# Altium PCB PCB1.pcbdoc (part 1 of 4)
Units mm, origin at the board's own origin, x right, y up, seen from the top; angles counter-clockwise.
Board outline 96.27 x 122.17 mm, 4 copper layers (Top Layer, Inner1, Inner2, Bottom Layer); 129 components, 127 nets, 708 pads, 342 vias.
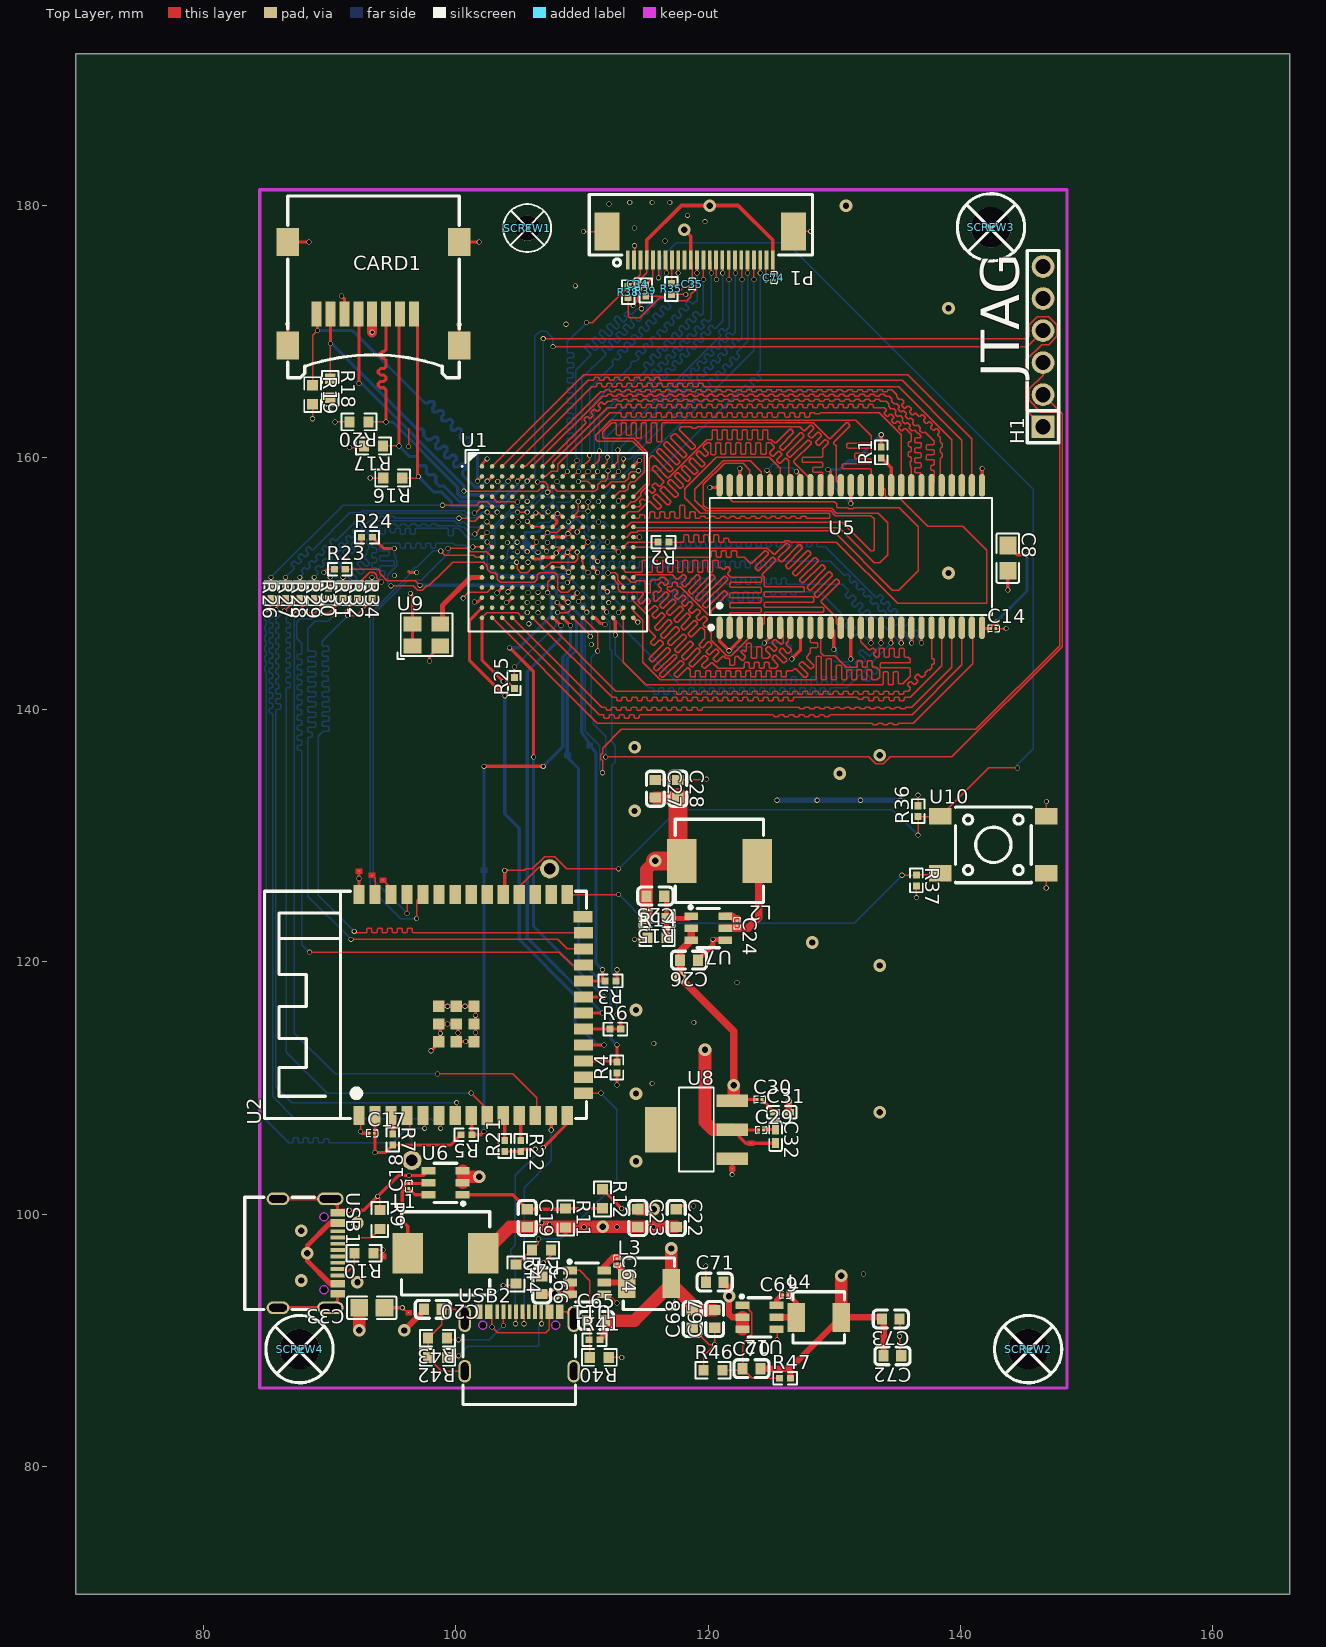
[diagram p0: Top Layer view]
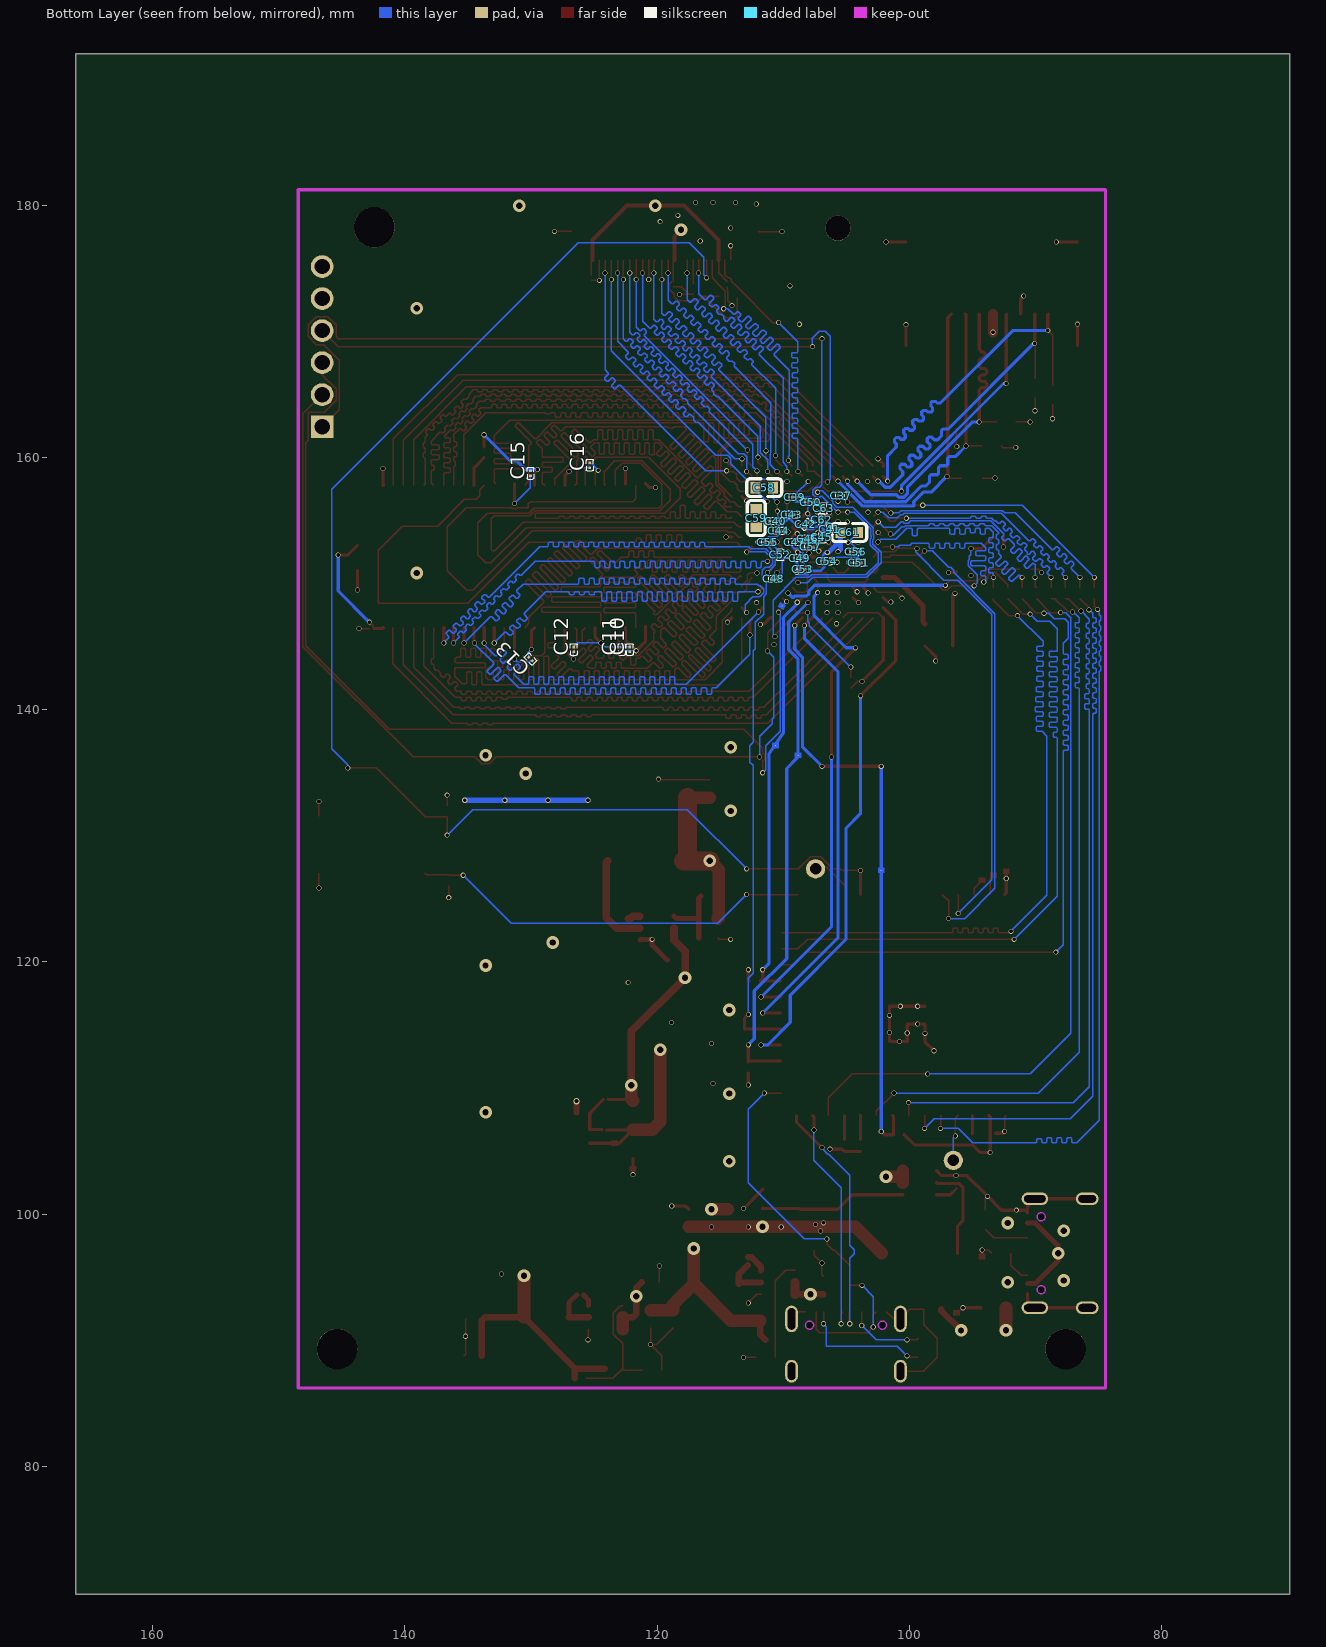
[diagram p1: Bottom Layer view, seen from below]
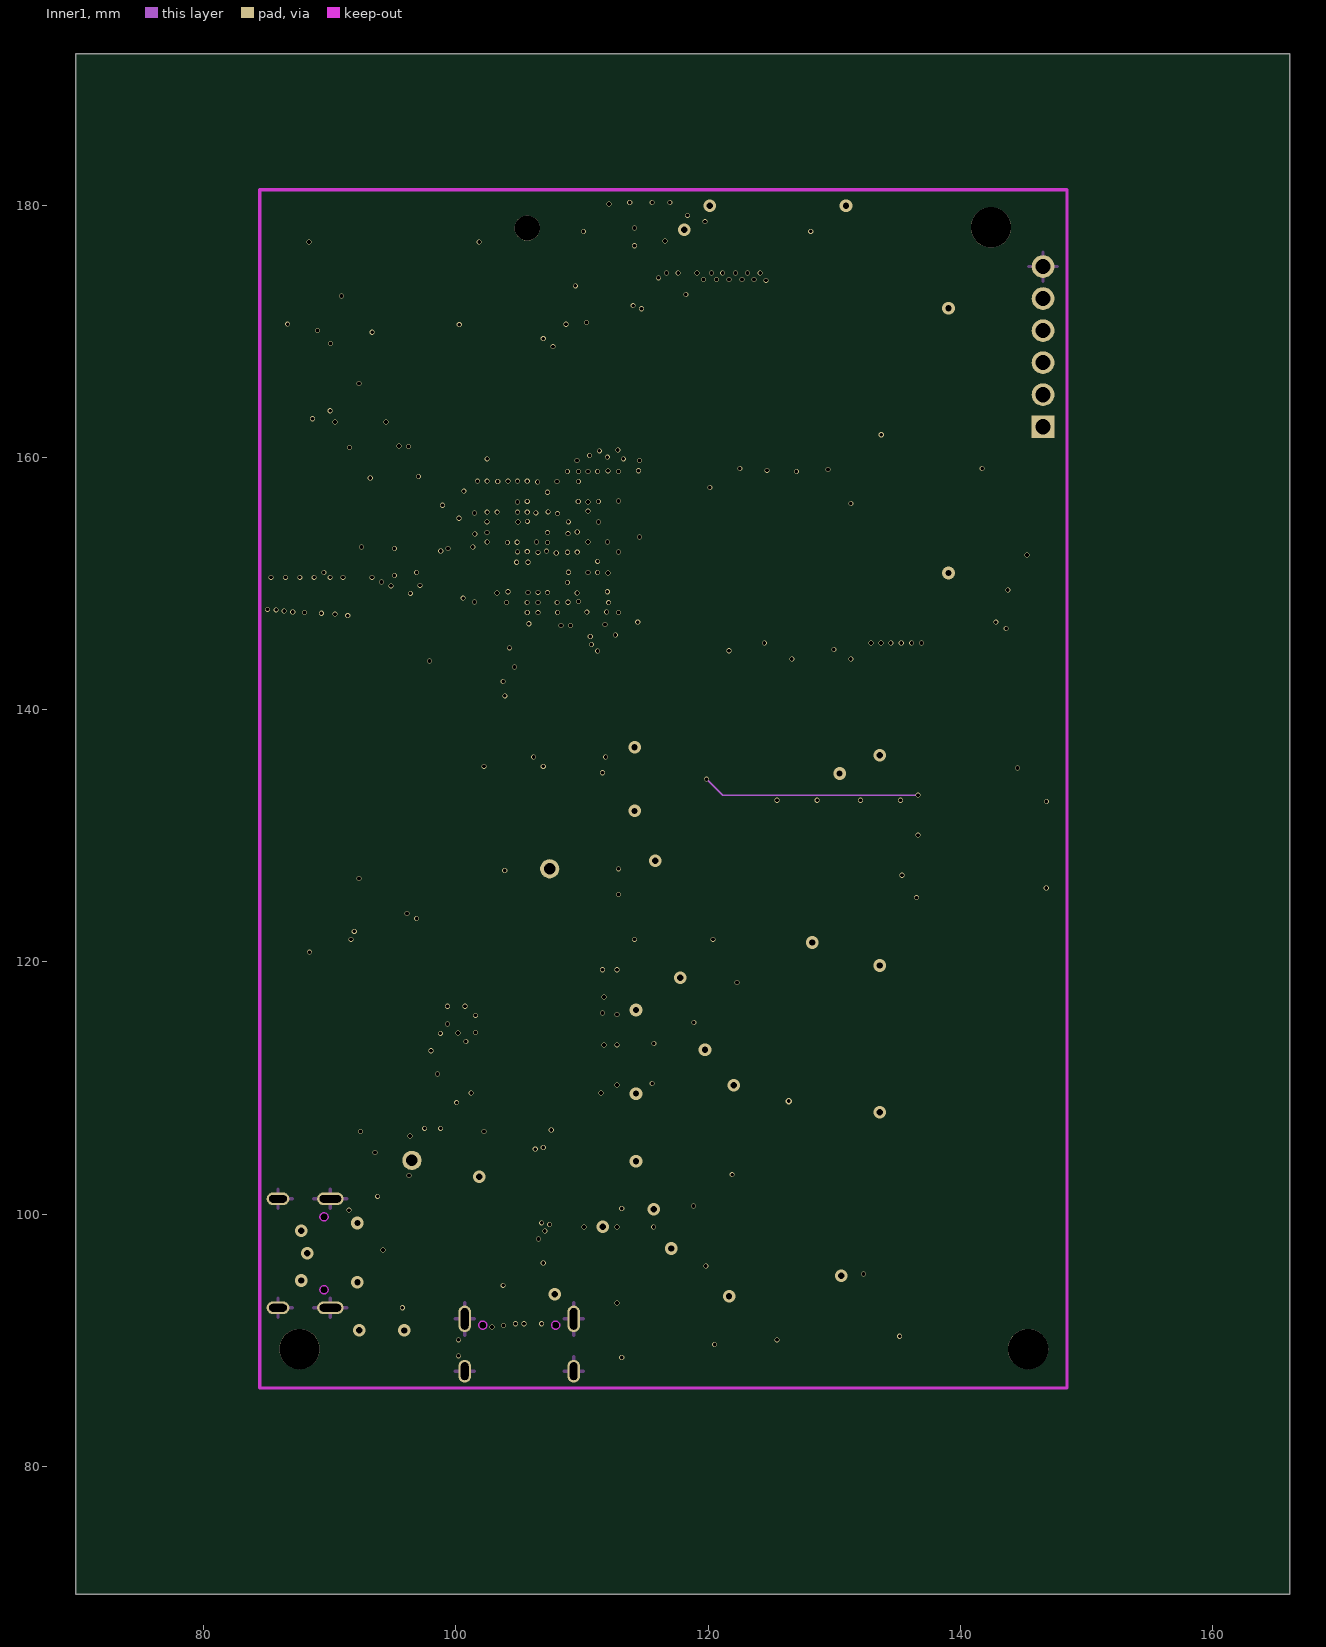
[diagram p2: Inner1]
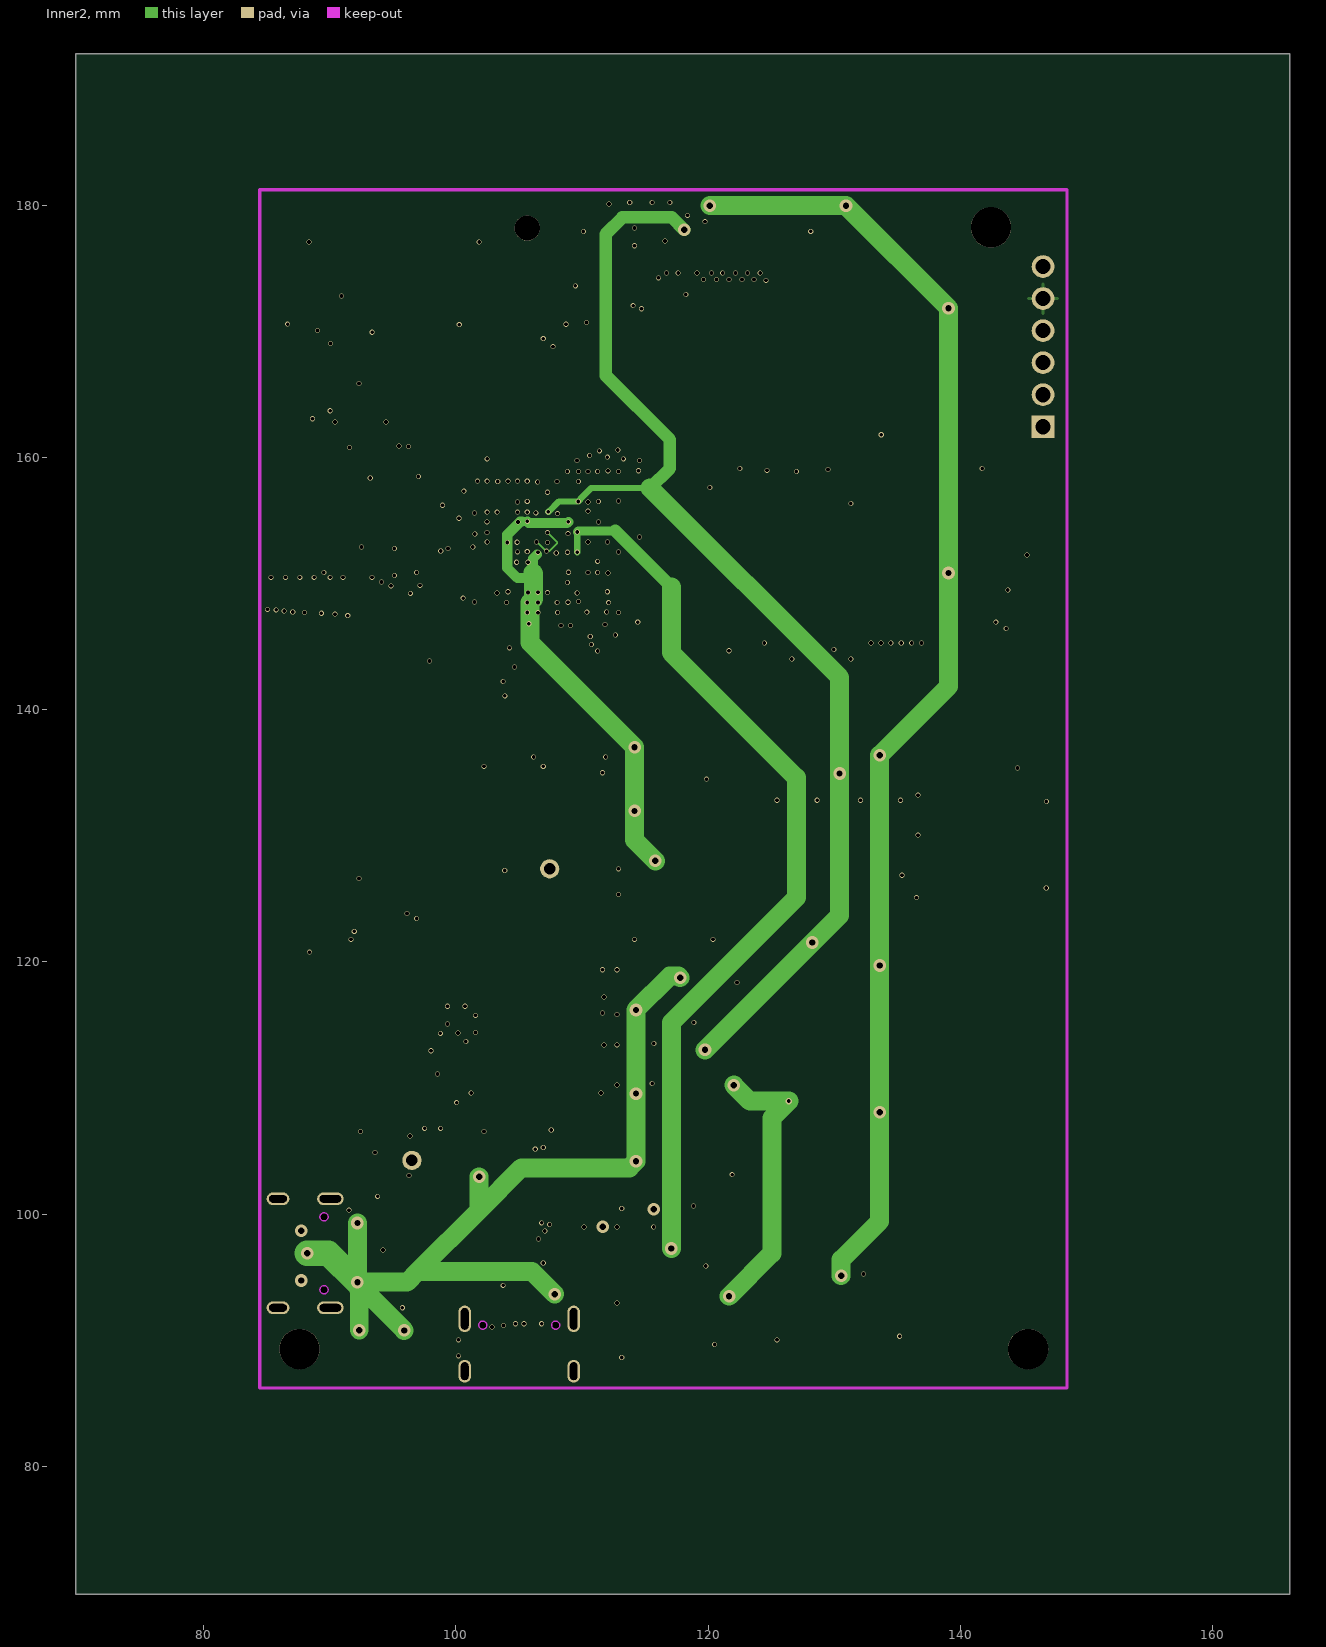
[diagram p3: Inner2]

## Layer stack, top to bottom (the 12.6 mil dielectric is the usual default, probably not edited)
Top Layer: signal copper (thickness not stored)
Dielectric: dielectric 0.32, FR-4, Dk 4.8
Inner1: signal copper (thickness not stored)
Dielectric: dielectric 0.32, FR-4, Dk 4.8
Inner2: signal copper (thickness not stored)
Dielectric: dielectric 0.32, FR-4, Dk 4.8
Bottom Layer: signal copper (thickness not stored)

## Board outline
166.116,69.85 69.85,69.85 69.85,192.024 166.116,192.024

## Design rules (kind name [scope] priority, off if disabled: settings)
BoardOutlineClearance copperThickness1oz [All] p0: genericclearance=0.254 ignorepadtopadclearanceinfootprint=FALSE except(0: Arc-SplitContinuation Track-SplitContinuation SMDPad-SplitContinuation THPad-SplitContinuation Via-SplitContinuation Fill-SplitContinuation Poly-SplitContinuation Region-SplitContinuation Text-SplitContinuation; 0.152: Track-CutoutEdge SMDPad-CutoutEdge THPad-CutoutEdge Via-CutoutEdge Region-CutoutEdge; 0.3: Track-OutlineEdge SMDPad-OutlineEdge THPad-OutlineEdge Via-OutlineEdge Fill-OutlineEdge Region-OutlineEdge Poly-OutlineEdge Text-OutlineEdge Fill-CutoutEdge)
BoardOutlineClearance copperThickness2oz [All] p0: genericclearance=0.254 ignorepadtopadclearanceinfootprint=FALSE except(0: Arc-SplitContinuation Track-SplitContinuation SMDPad-SplitContinuation THPad-SplitContinuation Via-SplitContinuation Fill-SplitContinuation Poly-SplitContinuation Region-SplitContinuation Text-SplitContinuation; 0.152: Track-CutoutEdge SMDPad-CutoutEdge THPad-CutoutEdge Via-CutoutEdge Region-CutoutEdge; 0.3: Track-OutlineEdge SMDPad-OutlineEdge THPad-OutlineEdge Via-OutlineEdge Fill-OutlineEdge Region-OutlineEdge Poly-OutlineEdge Text-OutlineEdge Fill-CutoutEdge)
Clearance copperThickness1oz [(InNet('SD_A0') OR InNet('SD_A1') OR InNet('SD_A2') OR InNet('SD_A3') OR InNet('SD_A4') OR InNet('SD_A5') OR InNet('SD_A6') OR InNet('SD_A7') OR InNet('SD_A8') OR InNet('SD_A9') OR InNet('SD_A10') OR InNet('SD_A11') OR InNet('SD_A12') OR InNet('SD_DQ15') OR InNet('SD_DQ14') OR InNet('SD_DQ8') OR InNet('SD_BA0') OR InNet('SD_BA1') OR InNet('SD_DQ9') OR InNet('SD_DQ7') OR InNet('SD_CLK') OR InNet('SD_WE_N') OR InNet('SD_DQ10') OR InNet('SD_CAS_N') OR InNet('SD_DQM1') OR InNet('SD_DQ2') OR InNet('SD_DQ3') OR InNet('SD_DQ11') OR InNet('SD_DQ12') OR InNet('SD_DQ13') OR InNet('SD_DQ0') OR InNet('SD_DQ1') OR InNet('SD_CS_N') OR InNet('SD_RAS_N') OR InNet('SD_DQ4') OR InNet('SD_DQ6') OR InNet('GND') OR InNet('SD_DQ5') OR InNet('SD_DQM0') OR InNet('$1N9437') OR InNet('+3V3') OR InNet('$1N11348') OR InNet('DOUT') OR InNet('DIN') OR InNet('CCLK') OR InNet('DONE') OR InNet('PROGRAMN') OR InNet('INITN') OR InNet('$1N11975') OR InNet('DN') OR InNet('DP') OR InNet('$1N14459') OR InNet('$1N14416') OR InNet('$1N14567') OR InNet('+5V') OR InNet('$1N16833') OR InNet('$1N16832') OR InNet('+1V1') OR InNet('$1N16834') OR InNet('+1V8') OR InNet('$1N17349') OR InNet('$1N12557') OR InNet('$1N12553') OR InNet('M_D2') OR InNet('M_D3') OR InNet('M_CMD') OR InNet('M_CLK') OR InNet('M_D0') OR InNet('M_D1') OR InNet('SDA') OR InNet('SCL') OR InNet('RESET') OR InNet('VSYNC') OR InNet('HREF') OR InNet('Y9') OR InNet('MCLK') OR InNet('Y8') OR InNet('Y7') OR InNet('PCLK') OR InNet('Y6') OR InNet('Y2') OR InNet('Y5') OR InNet('Y3') OR InNet('Y4') OR InNet('CRYSTAL') OR InNet('SSPI_CS_N') OR InNet('D0') OR InNet('D1') OR InNet('D2') OR InNet('D4') OR InNet('D3') OR InNet('D5') OR InNet('D6') OR InNet('D7') OR InNet('RX') OR InNet('TX') OR InNet('$1N29790') OR InNet('$1N29833') OR InNet('$1N29916') OR InNet('$1N29959') OR InNet('$1N30002') OR InNet('$1N30085') OR InNet('$1N30089') OR InNet('$1N30093') OR InNet('TDO') OR InNet('TDI') OR InNet('TMS') OR InNet('TCK') OR InNet('$1N33205') OR InNet('PROGRAM') OR InNet('$2N5507') OR InNet('$2N5509') OR InNet('$2N5511') OR InNet('FSDA') OR InNet('FSCL') OR InNet('+2V5') OR InNet('$1N60668') OR InNet('$1N60669') OR InNet('$1N60670') OR InNet('USB_VBUS') OR InNet('$1N63772') OR InNet('$1N63749') OR InNet('$1N63825') OR InNet('+2V8') OR InNet('$1N64402') OR InNet('$1N64401') OR InNet('$1N64403'))] p1: gap=0.178 ignorepadtopadclearanceinfootprint=FALSE except(0.099: Track-Track; 0.152: Track-SMDPad SMDPad-SMDPad Track-THPad SMDPad-THPad THPad-THPad Track-Via SMDPad-Via THPad-Via Via-Via SMDPad-Fill THPad-Fill Via-Fill Fill-Fill Track-Region SMDPad-Region THPad-Region Via-Region Region-Region Track-Poly SMDPad-Poly THPad-Poly Via-Poly Fill-Poly Region-Poly Poly-Poly Track-Text SMDPad-Text THPad-Text Via-Text Fill-Text Region-Text Poly-Text Text-Text; 0.175: Track-Hole SMDPad-Hole THPad-Hole Via-Hole Fill-Hole Region-Hole Poly-Hole Text-Hole Sheet-Hole; 0.3: Track-Fill Fill-Region Track-Sheet SMDPad-Sheet THPad-Sheet Via-Sheet Fill-Sheet Region-Sheet Poly-Sheet Text-Sheet)
Clearance copperThickness2oz [All] p1: gap=0.178 ignorepadtopadclearanceinfootprint=FALSE except(0.152: Track-SMDPad SMDPad-SMDPad Track-THPad SMDPad-THPad THPad-THPad Track-Via SMDPad-Via THPad-Via Via-Via SMDPad-Fill THPad-Fill Via-Fill Fill-Fill Track-Region SMDPad-Region THPad-Region Via-Region Region-Region Track-Poly SMDPad-Poly THPad-Poly Via-Poly Fill-Poly Region-Poly Poly-Poly Track-Text SMDPad-Text THPad-Text Via-Text Fill-Text Region-Text Poly-Text Text-Text; 0.175: Track-Hole SMDPad-Hole THPad-Hole Via-Hole Fill-Hole Region-Hole Poly-Hole Text-Hole Sheet-Hole; 0.203: Track-Track; 0.3: Track-Fill Fill-Region Track-Sheet SMDPad-Sheet THPad-Sheet Via-Sheet Fill-Sheet Region-Sheet Poly-Sheet Text-Sheet)
DiffPairsRouting differentialPair [All] p1: maxuncoupledlength=10 minlimit=6 maxlimit=6 mostfreqgap=6 toplayer_minwidth=5 toplayer_prefwidth=10 toplayer_maxwidth=100 bottomlayer_minwidth=5 bottomlayer_prefwidth=10 bottomlayer_maxwidth=100 midlayer1_minwidth=5 midlayer1_prefwidth=10 midlayer1_maxwidth=100 midlayer2_minwidth=5 midlayer2_prefwidth=10 midlayer2_maxwidth=100
PasteMaskExpansion pasteMaskExpansion [All] p1: expansion=0
PlaneConnect innerPlane [All] p1: planeconnectstyle=Relief reliefexpansion=0.508 reliefentries=4 reliefconductorwidth=0.254 reliefairgap=0.254
PolygonConnect copperRegion [All] p1: connectstyle=Relief reliefentries=4 reliefconductorwidth=10 polygonreliefangle="90 Angle" airgapwidth=10
RoutingVias viaSize [All] p1: viastyle="Through Hole" holewidth=11.811 minholewidth=11.811 maxholewidth=248.0314 width=15.748 minwidth=15.748 maxwidth=393.7008
SolderMaskExpansion solderMaskExpansion [All] p1: useseparateexpansions=TRUE expansion=2 expansionbottom=2
Width copperThickness1oz [All] p1: maxlimit=100 minlimit=4 preferedwidth=4
Width copperThickness2oz [All] p1: maxlimit=100 minlimit=8 preferedwidth=10

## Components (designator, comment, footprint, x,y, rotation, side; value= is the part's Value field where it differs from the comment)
C8 "CL21A476MQYNNNE" C0805 143.764,152.019 r270 top
C10 "GRM022R60J104KE15D" C01005 122.174,144.78 r90 bottom
C11 "GRM022R60J104KE15D" C01005 122.809,144.78 r90 bottom
C12 "GRM022R60J104KE15D" C01005 126.619,144.78 r90 bottom
C13 "GRM022R60J104KE15D" C01005 130.048,144.018 r45 bottom
C14 "GRM022R60J104KE15D" C01005 142.621,146.431 r0 top
C15 "GRM022R60J104KE15D" C01005 130.048,158.75 r90 bottom
C16 "GRM022R60J104KE15D" C01005 125.349,159.385 r90 bottom
C17 "GRM022R60J104KE15D" C01005 93.345,106.426 r0 top
C18 "GRM022R60J104KE15D" C01005 96.266,102.235 r90 top
C19 "TCC0603X7R104K500CT" C0603 105.664,99.695 r270 top
C20 "TCC0603X5R226M6R3CT" C0603 98.171,92.456 r180 top
C22 "TCC0603X5R226M6R3CT" C0603 117.475,99.695 r270 top
C23 "TCC0603X5R226M6R3CT" C0603 114.427,99.695 r270 top
C24 "GRM022R60J104KE15D" C01005 122.301,123.063 r270 top
C25 "TCC0603X7R104K500CT" C0603 115.824,125.222 r180 top
C26 "TCC0603X5R226M6R3CT" C0603 118.491,120.142 r180 top
C27 "TCC0603X5R226M6R3CT" C0603 115.824,133.731 r270 top
C28 "TCC0603X5R226M6R3CT" C0603 117.602,133.731 r270 top
C29 "GRM022R60J104KE15D" C01005 124.206,106.68 r0 top
C30 "GRM022R60J104KE15D" C01005 124.079,109.093 r0 top
C31 "GRM155R60J106ME44D" C0402 125.857,108.077 r0 top
C32 "GRM155R60J106ME44D" C0402 125.349,106.172 r270 top
C33 "CL21A476MQYNNNE" C0805 93.345,92.583 r180 top
C34 "GRM022R60J104KE15D" C01005 114.427,173.736 r270 top
C35 "GRM022R60J104KE15D" C01005 118.745,173.736 r270 top
C37 "GRM022R60J104KE15D" C01005 105.41,156.972 r180 bottom
C39 "GRM022R60J104KE15D" C01005 109.093,156.845 r180 bottom
C40 "GRM022R60J104KE15D" C01005 110.617,154.94 r180 bottom
C41 "GRM022R60J104KE15D" C01005 106.299,154.305 r90 bottom
C42 "GRM022R60J104KE15D" C01005 108.204,154.686 r135 bottom
C43 "GRM022R60J104KE15D" C01005 109.347,155.448 r180 bottom
C44 "GRM022R60J104KE15D" C01005 110.363,154.178 r180 bottom
C45 "GRM022R60J104KE15D" C01005 106.934,153.67 r270 bottom
C46 "GRM022R60J104KE15D" C01005 108.077,153.543 r180 bottom
C47 "GRM022R60J104KE15D" C01005 109.093,153.289 r0 bottom
C48 "GRM022R60J104KE15D" C01005 110.744,150.368 r180 bottom
C49 "GRM022R60J104KE15D" C01005 108.712,152.019 r180 bottom
C50 "GRM022R60J104KE15D" C01005 107.823,156.464 r180 bottom
C51 "GRM022R60J104KE15D" C01005 104.013,151.638 r180 bottom
C52 "GRM022R60J104KE15D" C01005 110.236,152.273 r270 bottom
C53 "GRM022R60J104KE15D" C01005 108.458,151.13 r180 bottom
C54 "GRM022R60J104KE15D" C01005 106.553,151.765 r180 bottom
C55 "GRM022R60J104KE15D" C01005 111.252,153.289 r0 bottom
C56 "GRM022R60J104KE15D" C01005 104.267,152.527 r180 bottom
C57 "GRM022R60J104KE15D" C01005 107.823,152.908 r0 bottom
C58 "TCC0603X5R226M6R3CT" C0603 111.506,157.607 r180 bottom
C59 "TCC0603X5R226M6R3CT" C0603 112.141,155.194 r90 bottom
C61 "TCC0603X5R226M6R3CT" C0603 104.775,154.051 r180 bottom
C62 "GRM022R60J104KE15D" C01005 106.934,155.067 r270 bottom
C63 "GRM022R60J104KE15D" C01005 106.807,155.956 r90 bottom
C64 "GRM022R60J104KE15D" C01005 112.776,96.266 r270 top
C65 "TCC0603X7R104K500CT" C0603 111.125,91.567 r0 top
C66 "TCC0603X5R226M6R3CT" C0603 106.807,94.361 r270 top
C67 "TCC0603X5R226M6R3CT" C0603 120.523,91.694 r90 top
C68 "TCC0603X5R226M6R3CT" C0603 118.745,91.694 r90 top
C69 "GRM022R60J104KE15D" C01005 126.111,93.599 r0 top
C70 "TCC0603X7R104K500CT" C0603 123.444,87.757 r0 top
C71 "TCC0603X5R226M6R3CT" C0603 120.523,94.615 r0 top
C72 "TCC0603X5R226M6R3CT" C0603 134.62,88.773 r180 top
C73 "TCC0603X5R226M6R3CT" C0603 134.493,91.694 r180 top
C74 "GRM022R60J104KE15D" C01005 125.222,174.244 r270 top
CARD1 "DS1139-06-08SS4BSR" TF-SMD_DS1139-06-08SS4BSR 93.472,172.974 r0 top
H1 "2.54-1x6P直针" HDR-TH_6P-P2.54-V-M-1 146.558,168.783 r90 top
L1 "FXL0630-6R8-M" IND-SMD_L7.0-W6.6 99.187,96.901 r0 top
L2 "FXL0630-100-M" IND-SMD_L7.3-W6.8 120.904,128.016 r180 top
L3 "SL0420-3R3M" IND-SMD_L4.5-W4.1_SL0420 115.316,94.488 r0 top
L4 "SL0420-3R3M" IND-SMD_L4.5-W4.1_SL0420 128.778,91.821 r0 top
P1 "AFC07-S24FCC-00" FPC-SMD_AFC07-S24FCC-00 119.38,176.784 r180 top
R1 "0402WGF1002TCE" R0402 133.731,160.401 r90 top
R2 "0402WGF330JTCE" R0402 116.459,153.289 r180 top
R3 "0402WGF1002TCE" R0402 112.268,118.491 r180 top
R4 "0402WGF1002TCE" R0402 112.776,111.633 r90 top
R5 "0402WGF1002TCE" R0402 100.838,106.299 r180 top
R6 "0402WGF330JTCE" R0402 112.649,114.681 r0 top
R7 "0402WGF1002TCE" R0402 94.996,105.918 r270 top
R9 "0603WAF5101T5E" R0603 93.98,99.568 r270 top
R10 "0603WAF5101T5E" R0603 92.71,96.901 r180 top
R11 "FRC0603F1963TS" R0603 108.712,99.695 r270 top
R12 "FRC0603F6202TS" R0603 111.633,101.219 r270 top
R14 "FRC0603F6202TS" R0603 115.951,121.92 r0 top
R15 "0603WAF2322T5E" R0603 115.951,123.444 r180 top
R16 "FRC0603F6202TS" R0603 94.996,158.369 r180 top
R17 "FRC0603F6202TS" R0603 93.472,160.909 r180 top
R18 "FRC0603F6202TS" R0603 90.043,165.481 r270 top
R19 "FRC0603F6202TS" R0603 88.646,164.973 r270 top
R20 "FRC0603F6202TS" R0603 92.329,162.814 r180 top
R21 "0402WGF1002TCE" R0402 103.886,105.41 r270 top
R22 "0402WGF1002TCE" R0402 105.156,105.41 r270 top
R23 "0402WGF1002TCE" R0402 90.805,151.13 r0 top
R24 "0402WGF1002TCE" R0402 92.964,153.67 r0 top
R25 "0402WGF1002TCE" R0402 104.648,142.113 r90 top
R26 "0402WGF330JTCE" R0402 85.344,149.225 r270 top
R27 "0402WGF330JTCE" R0402 86.487,149.225 r270 top
R28 "0402WGF330JTCE" R0402 87.63,149.225 r270 top
R29 "0402WGF330JTCE" R0402 88.773,149.225 r270 top
R30 "0402WGF330JTCE" R0402 89.916,149.225 r270 top
R31 "0402WGF330JTCE" R0402 91.059,149.225 r270 top
R32 "0402WGF330JTCE" R0402 92.202,149.225 r270 top
R34 "0402WGF330JTCE" R0402 93.345,149.225 r270 top
R35 "0402WGF1002TCE" R0402 117.094,173.355 r270 top
R36 "0402WGF1002TCE" R0402 136.652,131.953 r90 top
R37 "0402WGF1002TCE" R0402 136.525,126.469 r270 top
R38 "0402WGF1002TCE" R0402 113.665,173.101 r270 top
R39 "0402WGF1002TCE" R0402 115.062,173.228 r270 top
R40 "FRC0603F6202TS" R0603 111.379,88.646 r180 top
R41 "RC0402FR-07130KL" R0402 110.998,90.043 r0 top
R42 "0603WAF5101T5E" R0603 98.552,88.646 r180 top
R43 "0603WAF5101T5E" R0603 98.552,90.17 r180 top
R44 "FRC0603F1963TS" R0603 104.775,95.25 r270 top
R45 "FRC0603F1963TS" R0603 106.807,97.155 r180 top
R46 "FRC0603F6202TS" R0603 120.396,87.63 r0 top
R47 "0402WGF1543TCE" R0402 126.111,86.995 r0 top
SCREW1 "Screw-Hole-M2" Screw-Hole-M2 105.664,178.181 r0 top
SCREW2 "Screw-Hole-M3" Screw-Hole-M3 145.442,89.239 r0 top
SCREW3 "Screw-Hole-M3" Screw-Hole-M3 142.494,178.181 r0 top
SCREW4 "Screw-Hole-M3" Screw-Hole-M3 87.672,89.239 r0 top
U1 "LFE5U-25F-6BG256C" CABGA-256_L14.0-W14.0-R16-C16-P0.80-TL 108.077,153.289 r0 top
U2 "ESP32-S3-WROOM-1-N16R2" WIRELM-SMD_ESP32-S3-WROOM-1 101.219,116.586 r90 top
U5 "W9825G6KH-6" TSOP-54_L22.2-W10.2-P0.80-LS11.8-BL 131.318,152.146 r0 top
U6 "AP63200WU-7" SOT-23-6_L2.9-W1.6-P0.95-LS2.8-BR 99.187,102.489 r0 top
U7 "AP63200WU-7" SOT-23-6_L2.9-W1.6-P0.95-LS2.8-BR 120.015,122.682 r180 top
U8 "AMS1117-1.8_C6185" SOT-223-4_L6.5-W3.5-P2.30-LS7.0-BR 119.079,106.709 r0 top
U9 "XOS32024000LT00351005" OSC-SMD_4P-L3.2-W2.5-BL 97.663,145.923 r0 top
U10 "TPS645-5NC60" SW-SMD_4P-L6.0-W6.0-P4.50-LS9.2 142.621,129.286 r0 top
U11 "AP63200WU-7" SOT-23-6_L2.9-W1.6-P0.95-LS2.8-BR 110.416,94.587 r180 top
U12 "AP63200WU-7" SOT-23-6_L2.9-W1.6-P0.95-LS2.8-BR 124.079,91.821 r180 top
USB1 "TYPE-C16PIN" USB-C-SMD_TYPE-C16PIN#1 88.265,96.901 r270 top
USB2 "TYPE-C16PIN" USB-C-SMD_TYPE-C16PIN#2 105.029,89.916 r0 top

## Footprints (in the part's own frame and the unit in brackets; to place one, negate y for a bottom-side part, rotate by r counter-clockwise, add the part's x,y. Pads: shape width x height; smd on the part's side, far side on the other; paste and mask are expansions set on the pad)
C0402 [mm]
  rect 0.79x0.54 smd: 1(-0.545,0) 2(0.545,0)
  silkscreen extent -1.17,-0.5 1.17,0.5
C0603 [mm]
  rect 0.8x0.9 smd: 1(-0.7,0) 2(0.7,0)
  silkscreen extent -1.39,-0.71 1.39,0.71
C0805 [mm]
  rect 1.41x1.35 smd: 1(-1,0) 2(1,0)
  silkscreen extent -1.96,-0.9 1.96,0.9
C01005 [mm]
  rect 0.21x0.22 smd: 1(-0.195,0) 2(0.195,0)
  silkscreen extent -0.46,-0.27 0.46,0.27
CABGA-256_L14.0-W14.0-R16-C16-P0.80-TL [mm]
  round 0.36 smd: A1(-6,6) A2(-5.2,6) A3(-4.4,6) A4(-3.6,6) A5(-2.8,6) A6(-2,6) A7(-1.2,6) A8(-0.4,6) A9(0.4,6) A10(1.2,6) A11(2,6) A12(2.8,6) A13(3.6,6) A14(4.4,6) A15(5.2,6) A16(6,6) B1(-6,5.2) B2(-5.2,5.2) B3(-4.4,5.2) B4(-3.6,5.2) B5(-2.8,5.2) B6(-2,5.2) B7(-1.2,5.2) B8(-0.4,5.2) B9(0.4,5.2) B10(1.2,5.2) B11(2,5.2) B12(2.8,5.2) B13(3.6,5.2) B14(4.4,5.2) B15(5.2,5.2) B16(6,5.2) C1(-6,4.4) C2(-5.2,4.4) C3(-4.4,4.4) C4(-3.6,4.4) C5(-2.8,4.4) C6(-2,4.4) C7(-1.2,4.4) C8(-0.4,4.4) C9(0.4,4.4) C10(1.2,4.4) C11(2,4.4) C12(2.8,4.4) C13(3.6,4.4) C14(4.4,4.4) C15(5.2,4.4) C16(6,4.4) D1(-6,3.6) D2(-5.2,3.6) D3(-4.4,3.6) D4(-3.6,3.6) D5(-2.8,3.6) D6(-2,3.6) D7(-1.2,3.6) D8(-0.4,3.6) D9(0.4,3.6) D10(1.2,3.6) D11(2,3.6) D12(2.8,3.6) D13(3.6,3.6) D14(4.4,3.6) D15(5.2,3.6) D16(6,3.6) E1(-6,2.8) E2(-5.2,2.8) E3(-4.4,2.8) E4(-3.6,2.8) E5(-2.8,2.8) E6(-2,2.8) E7(-1.2,2.8) E8(-0.4,2.8) E9(0.4,2.8) E10(1.2,2.8) E11(2,2.8) E12(2.8,2.8) E13(3.6,2.8) E14(4.4,2.8) E15(5.2,2.8) E16(6,2.8) F1(-6,2) F2(-5.2,2) F3(-4.4,2) F4(-3.6,2) F5(-2.8,2) F6(-2,2) F7(-1.2,2) F8(-0.4,2) F9(0.4,2) F10(1.2,2) F11(2,2) F12(2.8,2) F13(3.6,2) F14(4.4,2) F15(5.2,2) F16(6,2) G1(-6,1.2) G2(-5.2,1.2) G3(-4.4,1.2) G4(-3.6,1.2) G5(-2.8,1.2) G6(-2,1.2) G7(-1.2,1.2) G8(-0.4,1.2) G9(0.4,1.2) G10(1.2,1.2) G11(2,1.2) G12(2.8,1.2) G13(3.6,1.2) G14(4.4,1.2) G15(5.2,1.2) G16(6,1.2) H1(-6,0.4) H2(-5.2,0.4) H3(-4.4,0.4) H4(-3.6,0.4) H5(-2.8,0.4) H6(-2,0.4) H7(-1.2,0.4) H8(-0.4,0.4) H9(0.4,0.4) H10(1.2,0.4) H11(2,0.4) H12(2.8,0.4) H13(3.6,0.4) H14(4.4,0.4) H15(5.2,0.4) H16(6,0.4) J1(-6,-0.4) J2(-5.2,-0.4) J3(-4.4,-0.4) J4(-3.6,-0.4) J5(-2.8,-0.4) J6(-2,-0.4) J7(-1.2,-0.4) J8(-0.4,-0.4) J9(0.4,-0.4) J10(1.2,-0.4) J11(2,-0.4) J12(2.8,-0.4) J13(3.6,-0.4) J14(4.4,-0.4) J15(5.2,-0.4) J16(6,-0.4) K1(-6,-1.2) K2(-5.2,-1.2) K3(-4.4,-1.2) K4(-3.6,-1.2) K5(-2.8,-1.2) K6(-2,-1.2) K7(-1.2,-1.2) K8(-0.4,-1.2) K9(0.4,-1.2) K10(1.2,-1.2) K11(2,-1.2) K12(2.8,-1.2) K13(3.6,-1.2) K14(4.4,-1.2) K15(5.2,-1.2) K16(6,-1.2) L1(-6,-2) L2(-5.2,-2) L3(-4.4,-2) L4(-3.6,-2) L5(-2.8,-2) L6(-2,-2) L7(-1.2,-2) L8(-0.4,-2) L9(0.4,-2) L10(1.2,-2) L11(2,-2) L12(2.8,-2) L13(3.6,-2) L14(4.4,-2) L15(5.2,-2) L16(6,-2) M1(-6,-2.8) M2(-5.2,-2.8) M3(-4.4,-2.8) M4(-3.6,-2.8) M5(-2.8,-2.8) M6(-2,-2.8) M7(-1.2,-2.8) M8(-0.4,-2.8) M9(0.4,-2.8) M10(1.2,-2.8) M11(2,-2.8) M12(2.8,-2.8) M13(3.6,-2.8) M14(4.4,-2.8) M15(5.2,-2.8) M16(6,-2.8) N1(-6,-3.6) N2(-5.2,-3.6) N3(-4.4,-3.6) N4(-3.6,-3.6) N5(-2.8,-3.6) N6(-2,-3.6) N7(-1.2,-3.6) N8(-0.4,-3.6) N9(0.4,-3.6) N10(1.2,-3.6) N11(2,-3.6) N12(2.8,-3.6) N13(3.6,-3.6) N14(4.4,-3.6) N15(5.2,-3.6) N16(6,-3.6) P1(-6,-4.4) P2(-5.2,-4.4) P3(-4.4,-4.4) P4(-3.6,-4.4) P5(-2.8,-4.4) P6(-2,-4.4) P7(-1.2,-4.4) P8(-0.4,-4.4) P9(0.4,-4.4) P10(1.2,-4.4) P11(2,-4.4) P12(2.8,-4.4) P13(3.6,-4.4) P14(4.4,-4.4) P15(5.2,-4.4) P16(6,-4.4) R1(-6,-5.2) R2(-5.2,-5.2) R3(-4.4,-5.2) R4(-3.6,-5.2) R5(-2.8,-5.2) R6(-2,-5.2) R7(-1.2,-5.2) R8(-0.4,-5.2) R9(0.4,-5.2) R10(1.2,-5.2) R11(2,-5.2) R12(2.8,-5.2) R13(3.6,-5.2) R14(4.4,-5.2) R15(5.2,-5.2) R16(6,-5.2) T1(-6,-6) T2(-5.2,-6) T3(-4.4,-6) T4(-3.6,-6) T5(-2.8,-6) T6(-2,-6) T7(-1.2,-6) T8(-0.4,-6) T9(0.4,-6) T10(1.2,-6) T11(2,-6) T12(2.8,-6) T13(3.6,-6) T14(4.4,-6) T15(5.2,-6) T16(6,-6)
  silkscreen extent -7.63,-7.08 7.08,7.3
FPC-SMD_AFC07-S24FCC-00 [mm]
  rect 0.3x1.5 smd: 1(5.745,1.129) 2(5.245,1.129) 3(4.746,1.129) 4(4.245,1.129) 5(3.746,1.129) 6(3.245,1.129) 7(2.746,1.129) 8(2.245,1.129) 9(1.746,1.129) 10(1.245,1.129) 11(0.746,1.129) 12(0.245,1.129) 13(-0.254,1.129) 14(-0.755,1.129) 15(-1.251,1.13) 16(-1.754,1.13) 17(-2.254,1.128) 18(-2.754,1.129) 19(-3.254,1.129) 20(-3.756,1.132) 21(-4.256,1.132) 22(-4.756,1.132) 23(-5.256,1.132) 24(-5.756,1.132)
  rect 2x3 smd: 25(-7.401,-1.132) 26(7.401,-1.125)
  silkscreen extent -8.89,-4.07 8.8,1.61
HDR-TH_6P-P2.54-V-M-1 [mm]
  rect 1.8x1.8 hole 1.2: 1(-6.35,0)
  round 1.8 hole 1.2: 2(-3.81,0) 3(-1.27,0) 4(1.27,0) 5(3.81,0) 6(6.35,0)
  silkscreen extent -7.62,-1.25 7.62,1.25
IND-SMD_L4.5-W4.1_SL0420 [mm]
  rect 1.4x2.3 smd: 1(-1.775,0) 2(1.775,0)
  silkscreen extent -2.03,-2.03 2.03,2.03
IND-SMD_L7.0-W6.6 [mm]
  rect 2.4x3.2 smd: 1(-3,0) 2(3,0)
  silkscreen extent -3.5,-3.3 3.5,3.3
IND-SMD_L7.3-W6.8 [mm]
  rect 2.35x3.5 smd: 1(-3,0) 2(3,0)
  silkscreen extent -3.5,-3.3 3.5,3.3
OSC-SMD_4P-L3.2-W2.5-BL [mm]
  rect 1.4x1.2 smd: 1(-1.1,-0.875) 2(1.1,-0.875) 3(1.1,0.875) 4(-1.1,0.875)
  silkscreen extent -2.29,-1.9 2.07,1.72
R0402 [mm]
  rect 0.566x0.54 smd: 1(-0.433,0) 2(0.433,0)
  silkscreen extent -0.94,-0.5 0.94,0.5
R0603 [mm]
  rect 0.806x0.864 smd: 1(-0.753,0) 2(0.753,0)
  silkscreen extent -1.39,-0.66 1.39,0.66
Screw-Hole-M2 [mm]
  round 2 hole 2: 1(0,0)
  silkscreen extent -1.9,-1.9 1.9,1.9
Screw-Hole-M3 [mil]
  round 126 hole 126: 1(-2.5,2.5)
  silkscreen extent -107,-102 102,107
SOT-23-6_L2.9-W1.6-P0.95-LS2.8-BR [mm]
  rect 1.1x0.6 smd: 1(1.35,-0.95) 2(1.35,0) 3(1.35,0.95) 4(-1.35,0.95) 5(-1.35,0) 6(-1.35,-0.95)
  silkscreen extent -0.9,-1.78 1.52,1.55
SOT-223-4_L6.5-W3.5-P2.30-LS7.0-BR [mm]
  rect 2.47x0.98 smd: 1(2.835,-2.3) 2(2.835,0) 3(2.835,2.3)
  rect 2.47x3.6 smd: 4(-2.835,0)
  silkscreen extent -1.37,-3.33 1.37,3.33
SW-SMD_4P-L6.0-W6.0-P4.50-LS9.2 [mm]
  rect 1.8x1.3 smd: 1(-4.2,2.25) 2(4.2,2.25) 3(-4.2,-2.25) 4(4.2,-2.25)
  silkscreen extent -3,-3 3,3
TF-SMD_DS1139-06-08SS4BSR [mm]
  rect 0.8x2 smd: 1(3.2,-1.6) 2(2.1,-1.6) 3(1,-1.6) 4(-0.1,-1.6) 5(-1.2,-1.6) 6(-2.3,-1.6) 7(-3.4,-1.6) 8(-4.5,-1.6)
  rect 1.8x2.2 smd: 9(-6.8,4.1) 10(-6.8,-4.1) 11(6.8,-4.1) 12(6.8,4.1)
  silkscreen extent -6.8,-6.65 6.8,7.75
TSOP-54_L22.2-W10.2-P0.80-LS11.8-BL [mm]
  oval 0.5x1.8 smd: 1(-10.4,-5.642) 2(-9.6,-5.642) 3(-8.8,-5.642) 4(-8,-5.642) 5(-7.2,-5.642) 6(-6.4,-5.642) 7(-5.6,-5.642) 8(-4.8,-5.642) 9(-4,-5.642) 10(-3.2,-5.642) 11(-2.4,-5.642) 12(-1.6,-5.642) 13(-0.8,-5.642) 14(0,-5.642) 15(0.8,-5.642) 16(1.6,-5.642) 17(2.4,-5.642) 18(3.2,-5.642) 19(4,-5.642) 20(4.8,-5.642) 21(5.6,-5.642) 22(6.4,-5.642) 23(7.2,-5.642) 24(8,-5.642) 25(8.8,-5.642) 26(9.6,-5.642) 27(10.4,-5.642) 28(10.4,5.642) 29(9.6,5.642) 30(8.8,5.642) 31(8,5.642) 32(7.2,5.642) 33(6.4,5.642) 34(5.6,5.642) 35(4.8,5.642) 36(4,5.642) 37(3.2,5.642) 38(2.4,5.642) 39(1.6,5.642) 40(0.8,5.642) 41(0,5.642) 42(-0.8,5.642) 43(-1.6,5.642) 44(-2.4,5.642) 45(-3.2,5.642) 46(-4,5.642) 47(-4.8,5.642) 48(-5.6,5.642) 49(-6.4,5.642) 50(-7.2,5.642) 51(-8,5.642) 52(-8.8,5.642) 53(-9.6,5.642) 54(-10.4,5.642)
  silkscreen extent -11.23,-5.79 11.19,4.65
USB-C-SMD_TYPE-C16PIN#1 [mm]
  oval 1x2.1 hole 0.6 slot 1.7 at 90 deg: 1(-4.32,1.787) 2(4.32,1.787)
  oval 1x1.8 hole 0.6 slot 1.4 at 90 deg: 3(-4.32,-2.362) 4(4.32,-2.362)
  rect 0.6x1.15 smd: A1B12(-3.2,2.362) A4B9(-2.4,2.362) B1A12(3.2,2.362) B4A9(2.4,2.362)
  rect 0.3x1.15 smd: A5(-1.25,2.362) A6(-0.25,2.362) A7(0.25,2.362) A8(1.25,2.362) B5(1.75,2.362) B6(0.75,2.362) B7(-0.75,2.362) B8(-1.75,2.362)
  Board Outline Layer circle w0.005: c2.89,1.288 r0.325
  Board Outline Layer circle w0.005: c-2.89,1.288 r0.325
  Board Outline Layer region: 2.89,1.613 3.031,1.581 3.144,1.491 3.207,1.36 3.207,1.216 3.144,1.085 3.031,0.995 2.89,0.963 2.89,0.963 2.749,0.995 2.636,1.085 2.573,1.216 2.573,1.36 2.636,1.491 2.749,1.581 2.89,1.613
  Board Outline Layer region: -2.89,1.613 -2.749,1.581 -2.636,1.491 -2.573,1.36 -2.573,1.216 -2.636,1.085 -2.749,0.995 -2.89,0.963 -2.89,0.963 -3.031,0.995 -3.144,1.085 -3.207,1.216 -3.207,1.36 -3.144,1.491 -3.031,1.581 -2.89,1.613
  Multi-Layer board cut-out: 2.89,1.613 3.031,1.581 3.144,1.491 3.207,1.36 3.207,1.216 3.144,1.085 3.031,0.995 2.89,0.963 2.89,0.963 2.749,0.995 2.636,1.085 2.573,1.216 2.573,1.36 2.636,1.491 2.749,1.581 2.89,1.613
  Multi-Layer board cut-out: -2.89,1.613 -2.749,1.581 -2.636,1.491 -2.573,1.36 -2.573,1.216 -2.636,1.085 -2.749,0.995 -2.89,0.963 -2.89,0.963 -3.031,0.995 -3.144,1.085 -3.207,1.216 -3.207,1.36 -3.144,1.491 -3.031,1.581 -2.89,1.613
  silkscreen extent -4.45,-5 4.45,0.52
USB-C-SMD_TYPE-C16PIN#2 [mm]
  oval 1x2.1 hole 0.6 slot 1.7 at 90 deg: 1(-4.32,1.787) 2(4.32,1.787)
  oval 1x1.8 hole 0.6 slot 1.4 at 90 deg: 3(-4.32,-2.362) 4(4.32,-2.362)
  rect 0.6x1.15 smd: A1B12(-3.2,2.362) A4B9(-2.4,2.362) B1A12(3.2,2.362) B4A9(2.4,2.362)
  rect 0.3x1.15 smd: A5(-1.25,2.362) A6(-0.25,2.362) A7(0.25,2.362) A8(1.25,2.362) B5(1.75,2.362) B6(0.75,2.362) B7(-0.75,2.362) B8(-1.75,2.362)
  Board Outline Layer circle w0.005: c2.89,1.288 r0.325
  Board Outline Layer circle w0.005: c-2.89,1.288 r0.325
  Board Outline Layer region: 3.215,1.288 3.183,1.147 3.093,1.034 2.962,0.971 2.818,0.971 2.687,1.034 2.597,1.147 2.565,1.288 2.565,1.288 2.597,1.429 2.687,1.542 2.818,1.605 2.962,1.605 3.093,1.542 3.183,1.429 3.215,1.288
  Board Outline Layer region: -2.565,1.288 -2.597,1.147 -2.687,1.034 -2.818,0.971 -2.962,0.971 -3.093,1.034 -3.183,1.147 -3.215,1.288 -3.215,1.288 -3.183,1.429 -3.093,1.542 -2.962,1.605 -2.818,1.605 -2.687,1.542 -2.597,1.429 -2.565,1.288
  Multi-Layer board cut-out: 3.215,1.288 3.183,1.147 3.093,1.034 2.962,0.971 2.818,0.971 2.687,1.034 2.597,1.147 2.565,1.288 2.565,1.288 2.597,1.429 2.687,1.542 2.818,1.605 2.962,1.605 3.093,1.542 3.183,1.429 3.215,1.288
  Multi-Layer board cut-out: -2.565,1.288 -2.597,1.147 -2.687,1.034 -2.818,0.971 -2.962,0.971 -3.093,1.034 -3.183,1.147 -3.215,1.288 -3.215,1.288 -3.183,1.429 -3.093,1.542 -2.962,1.605 -2.818,1.605 -2.687,1.542 -2.597,1.429 -2.565,1.288
  silkscreen extent -4.45,-5 4.45,0.52
WIRELM-SMD_ESP32-S3-WROOM-1 [mm]
  rect 1.5x0.9 smd: 1(-8.75,8.895) 2(-8.75,7.625) 3(-8.75,6.355) 4(-8.75,5.085) 5(-8.75,3.815) 6(-8.75,2.545) 7(-8.75,1.275) 8(-8.75,0.005) 9(-8.75,-1.265) 10(-8.75,-2.535) 11(-8.75,-3.805) 12(-8.75,-5.075) 13(-8.75,-6.345) 14(-8.75,-7.615) 27(8.75,-7.615) 28(8.75,-6.345) 29(8.75,-5.075) 30(8.75,-3.805) 31(8.75,-2.535) 32(8.75,-1.265) 33(8.75,0.005) 34(8.75,1.275) 35(8.75,2.545) 36(8.75,3.815) 37(8.75,5.085) 38(8.75,6.355) 39(8.75,7.625) 40(8.75,8.895)
  rect 0.9x1.5 smd: 15(-6.985,-8.895) 16(-5.715,-8.895) 17(-4.445,-8.895) 18(-3.175,-8.895) 19(-1.905,-8.895) 20(-0.635,-8.895) 21(0.635,-8.895) 22(1.905,-8.895) 23(3.175,-8.895) 24(4.445,-8.895) 25(5.715,-8.895) 26(6.985,-8.865)
  rect 0.9x0.9 smd: 41(-2.9,-0.225) 41(-2.9,1.175) 41(-2.9,2.575) 41(-1.5,2.575) 41(-1.5,-0.225) 41(-1.5,1.175) 41(-0.1,2.575) 41(-0.1,1.175) 41(-0.1,-0.225)
  silkscreen extent -9,-9.14 9.02,16.39

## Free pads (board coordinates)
  round 1.524 hole 0.914: 1(96.52,104.267) 1(107.442,127.381)
  round 0.08 smd: 55(92.324,127.195) 55(93.345,126.873) 55(94.234,96.647) 55(94.234,126.492) 55(96.266,92.202) 55(121.914,103.597) 55(123.394,105.627)
  round 0.08 smd far side: 55(102.235,127.254) 55(108.839,136.377) 55(110.109,148.209) 55(110.617,137.16)

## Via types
v1: diameter 0.4, hole 0.3, Top Layer to Bottom Layer, 308 vias
v2: diameter 1, hole 0.5, Top Layer to Bottom Layer, 33 vias
v3: diameter 0.5, hole 0.3, Top Layer to Bottom Layer, 1 vias

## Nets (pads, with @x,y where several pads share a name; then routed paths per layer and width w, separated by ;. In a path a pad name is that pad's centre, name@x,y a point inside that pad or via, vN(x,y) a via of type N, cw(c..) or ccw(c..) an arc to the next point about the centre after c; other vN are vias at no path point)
$1N9437: R1.1 U5.37 | length 2.5
  Top Layer w0.254: R1.1@133.731,159.968 134.518,159.181 U5.37@134.518,157.788
$1N11348: R2.1 U5.38 | length 46.8
  Top Layer w0.1: R2.1@116.892,153.289 117.989,153.289 118.059,153.36 118.059,153.807 118.13,153.878 118.389,153.878 118.459,153.807 118.459,153.36 118.53,153.289 118.789,153.289 118.859,153.36 118.859,153.807 118.93,153.878 119.189,153.878 119.259,153.807 119.259,153.36 119.33,153.289 119.589,153.289 119.659,153.36 119.659,153.807 119.73,153.878 119.989,153.878 120.059,153.807 120.059,153.36 120.13,153.289 120.389,153.289 120.459,153.36 120.459,153.807 120.53,153.878 120.789,153.878 120.859,153.807 120.859,153.36 120.93,153.289 121.189,153.289 121.259,153.36 121.259,153.532 121.33,153.602 121.589,153.602 121.659,153.532 121.659,153.36 121.73,153.289 125.989,153.289 126.102,153.402 126.417,153.402 126.53,153.289 130.175,153.289 135.029,148.435 142.085,148.435 142.113,148.463 142.113,152.654 140.208,154.559 137.414,154.559 135.287,156.686 134.331,156.686 134.066,156.951 134.066,157.44 U5.38@133.718,157.788
$1N11975: R7.1 U2.3 | length 1.5
  Top Layer w0.254: U2.3@94.991,107.836 94.996,107.831 R7.1@94.996,106.351
$1N12553: R10.2 USB1.B5 | length 2.6
  Top Layer w0.1: USB1.B5@90.627,95.151 91.138,95.151 91.957,95.97 R10.2@91.957,96.901
$1N12557: R9.2 USB1.A5 | length 3.6
  Top Layer w0.1: USB1.A5@90.627,98.151 93.316,98.151 R9.2@93.98,98.815
$1N14416: C18.2 L1.1 U6.5 | length 7.6
  Top Layer w0.254: L1.1@96.187,96.901 96.187,99.06 95.758,99.489 95.758,102.141 96.04,102.424 96.26,102.424 C18.2@96.266,102.43 97.778,102.43 U6.5@97.837,102.489
$1N14459: C18.1 U6.6 | length 1.8
  Top Layer w0.254: C18.1@96.266,102.04 96.767,101.539 U6.6@97.837,101.539
$1N14567: C19.1 R11.1 R12.2 U6.1 | length 11.6
  Top Layer w0.254: U6.1@100.537,101.539 104.52,101.539 C19.1@105.664,100.395 108.659,100.395 R11.1@108.712,100.448 111.616,100.448 R12.2@111.633,100.466
$1N16832: C24.2 L2.1 U7.5 | length 7.6
  Top Layer w0.6: U7.5@121.365,122.682 123.19,122.682 124.031,123.523 124.031,127.889 L2.1@123.904,128.016
$1N16833: C24.1 U7.6 | length 1
  Top Layer w0.6: U7.6@121.365,123.632 121.927,123.632 122.134,123.425 122.301,123.425
$1N16834: C25.1 R14.2 R15.1 U7.1 | length 5.4
  Top Layer w0.4: C25.1@116.524,125.222 116.704,125.042 R15.1@116.704,123.444 ; R14.2@116.704,121.92 R15.1@116.704,123.444 ; U7.1@118.665,123.632 118.477,123.444 R15.1@116.704,123.444
$1N17349: C29.2 C30.2 C31.1 C32.1 | length 3.8
  Top Layer w0.254: C30.2@124.274,109.093 125.349,108.018 C32.1@125.349,106.717 124.438,106.717 C29.2@124.401,106.68
$1N29790: R26.2 U2.5 | length 59.2
  Top Layer w0.1: v1(85.082,147.955) 85.344,148.217 R26.2@85.344,148.792 ; U2.5@97.531,107.836 97.536,107.831 v1(97.536,106.807)
  Bottom Layer w0.1: v1(85.082,147.955) 84.963,147.836 84.963,147.523 84.834,147.395 84.834,147.123 84.963,146.995 84.963,146.723 84.834,146.595 84.834,146.323 84.963,146.195 84.963,145.923 84.834,145.795 84.834,145.523 84.963,145.395 84.963,145.123 84.834,144.995 84.834,144.723 84.963,144.595 84.963,144.323 84.834,144.195 84.834,143.923 84.963,143.795 84.963,143.523 84.834,143.395 84.834,143.123 84.963,142.995 84.963,107.442 86.741,105.664 87.041,105.664 87.112,105.735 87.112,105.974 87.182,106.045 87.441,106.045 87.512,105.974 87.512,105.735 87.582,105.664 87.841,105.664 87.912,105.735 87.912,105.974 87.982,106.045 88.241,106.045 88.312,105.974 88.312,105.735 88.382,105.664 88.641,105.664 88.712,105.735 88.712,105.974 88.782,106.045 89.041,106.045 89.112,105.974 89.112,105.735 89.182,105.664 89.441,105.664 89.512,105.735 89.512,105.904 89.582,105.974 89.841,105.974 89.912,105.904 89.912,105.735 89.982,105.664 94.995,105.664 96.138,106.807 v1(97.536,106.807)
$1N29833: R27.2 U2.6 | length 59.2
  Top Layer w0.1: v1(85.761,147.919) 85.761,148.066 R27.2@86.487,148.792 ; v1(98.801,106.807) U2.6@98.801,107.836
  Bottom Layer w0.1: v1(85.761,147.919) 85.471,147.629 85.471,147.358 85.4,147.287 85.263,147.287 85.192,147.217 85.192,146.958 85.263,146.887 85.4,146.887 85.471,146.817 85.471,146.558 85.4,146.487 85.263,146.487 85.192,146.417 85.192,146.158 85.263,146.087 85.4,146.087 85.471,146.017 85.471,145.758 85.4,145.687 85.263,145.687 85.192,145.617 85.192,145.358 85.263,145.287 85.4,145.287 85.471,145.217 85.471,144.958 85.4,144.887 85.263,144.887 85.192,144.817 85.192,144.558 85.263,144.487 85.4,144.487 85.471,144.417 85.471,144.158 85.4,144.087 85.263,144.087 85.192,144.017 85.192,143.758 85.263,143.687 85.4,143.687 85.471,143.617 85.471,143.358 85.4,143.287 85.263,143.287 85.192,143.217 85.192,142.958 85.263,142.887 85.4,142.887 85.471,142.817 85.471,142.558 85.4,142.487 85.263,142.487 85.192,142.417 85.192,142.158 85.263,142.087 85.4,142.087 85.471,142.017 85.471,141.794 85.4,141.723 85.263,141.723 85.192,141.653 85.192,141.394 85.263,141.323 85.4,141.323 85.471,141.253 85.471,140.994 85.4,140.923 85.263,140.923 85.192,140.853 85.192,140.594 85.263,140.523 85.4,140.523 85.471,140.453 85.471,140.194 85.4,140.123 85.263,140.123 85.192,140.053 85.192,139.794 85.263,139.723 85.4,139.723 85.471,139.653 85.471,109.347 87.249,107.569 98.039,107.569 v1(98.801,106.807)
$1N29916: R29.2 U2.9 | length 59.1
  Top Layer w0.1: v1(87.072,147.751) 87.427,147.751 88.469,148.792 R29.2@88.773,148.792 ; v1(101.219,109.601) 102.611,108.209 U2.9@102.611,107.836
  Bottom Layer w0.1: v1(87.072,147.751) 86.87,147.549 86.814,147.549 86.541,147.276 86.541,146.979 86.612,146.909 86.797,146.909 86.868,146.838 86.868,146.579 86.797,146.509 86.612,146.509 86.541,146.438 86.541,146.179 86.612,146.109 86.797,146.109 86.868,146.038 86.868,145.779 86.797,145.709 86.612,145.709 86.541,145.638 86.541,145.379 86.612,145.309 86.797,145.309 86.868,145.238 86.868,144.979 86.797,144.909 86.612,144.909 86.541,144.838 86.541,144.579 86.612,144.509 86.797,144.509 86.868,144.438 86.868,144.179 86.797,144.109 86.612,144.109 86.541,144.038 86.541,143.779 86.612,143.709 86.797,143.709 86.868,143.638 86.868,143.379 86.797,143.309 86.612,143.309 86.541,143.238 86.541,143.024 86.612,142.954 86.797,142.954 86.868,142.883 86.868,142.624 86.797,142.554 86.612,142.554 86.541,142.483 86.541,142.224 86.612,142.154 86.797,142.154 86.868,142.083 86.868,141.824 86.797,141.754 86.612,141.754 86.541,141.683 86.541,112.849 89.789,109.601 v1(101.219,109.601)
$1N29959: R30.2 U2.12 | length 59
  Top Layer w0.1: v1(88.011,147.701) 88.825,147.701 R30.2@89.916,148.792 ; v1(98.552,111.125) 104.521,111.125 106.421,109.225 U2.12@106.421,107.836
  Bottom Layer w0.1: v1(88.011,147.701) 87.591,147.701 87.239,147.349 87.239,147.339 87.195,147.295 87.195,114.354 90.424,111.125 v1(98.552,111.125)
$1N30002: R31.2 U2.23 | length 58.9
  Top Layer w0.1: v1(88.392,120.777) 108.204,120.777 109.22,119.761 U2.23@110.114,119.761 ; v1@89.281,147.701 89.968,147.701 R31.2@91.059,148.792
  Bottom Layer w0.1: v1(88.392,120.777) 87.796,121.373 87.796,136.711 87.725,136.782 87.495,136.782 87.424,136.852 87.424,137.111 87.495,137.182 87.725,137.182 87.796,137.252 87.796,137.511 87.725,137.582 87.495,137.582 87.424,137.652 87.424,137.911 87.495,137.982 87.725,137.982 87.796,138.052 87.796,138.311 87.725,138.382 87.495,138.382 87.424,138.452 87.424,138.711 87.495,138.782 87.725,138.782 87.796,138.852 87.796,139.111 87.725,139.182 87.495,139.182 87.424,139.252 87.424,139.511 87.495,139.582 87.725,139.582 87.796,139.652 87.796,139.911 87.725,139.982 87.495,139.982 87.424,140.052 87.424,140.311 87.495,140.382 87.725,140.382 87.796,140.452 87.796,140.711 87.725,140.782 87.495,140.782 87.424,140.852 87.424,141.111 87.495,141.182 87.725,141.182 87.796,141.252 87.796,141.511 87.725,141.582 87.495,141.582 87.424,141.652 87.424,141.911 87.495,141.982 87.725,141.982 87.796,142.052 87.796,142.311 87.725,142.382 87.495,142.382 87.424,142.452 87.424,142.711 87.495,142.782 87.725,142.782 87.796,142.852 87.796,143.111 87.725,143.182 87.495,143.182 87.424,143.252 87.424,143.511 87.495,143.582 87.725,143.582 87.796,143.652 87.796,143.911 87.725,143.982 87.495,143.982 87.424,144.052 87.424,144.311 87.495,144.382 87.725,144.382 87.796,144.452 87.796,145.249 87.395,145.65 87.395,146.933 87.674,147.212 88.523,147.212 88.956,147.645 v1(89.337,147.645)
$1N30085: R34.2 U2.25 | length 59.1
  Top Layer w0.1: v1@91.44,147.447 92.127,147.447 93.345,148.665 R34.2@93.345,148.792 ; v1(91.948,122.428) 92.075,122.301 92.883,122.301 92.954,122.372 92.954,122.611 93.025,122.682 93.283,122.682 93.354,122.611 93.354,122.372 93.425,122.301 93.683,122.301 93.754,122.372 93.754,122.611 93.825,122.682 94.083,122.682 94.154,122.611 94.154,122.372 94.225,122.301 94.483,122.301 94.554,122.372 94.554,122.611 94.625,122.682 94.883,122.682 94.954,122.611 94.954,122.372 95.025,122.301 95.283,122.301 95.354,122.372 95.354,122.611 95.425,122.682 95.683,122.682 95.754,122.611 95.754,122.372 95.825,122.301 96.083,122.301 96.154,122.372 96.154,122.611 96.225,122.682 96.483,122.682 96.554,122.611 96.554,122.372 96.625,122.301 U2.25@110.114,122.301
  Bottom Layer w0.1: v1(91.433,147.454) 89.408,145.43 89.408,145.109 89.479,145.038 89.845,145.038 89.916,144.968 89.916,144.709 89.845,144.638 89.479,144.638 89.408,144.568 89.408,144.309 89.479,144.238 89.835,144.238 89.906,144.168 89.906,143.909 89.835,143.838 89.479,143.838 89.408,143.768 89.408,143.509 89.479,143.438 89.844,143.438 89.915,143.368 89.915,143.109 89.844,143.038 89.479,143.038 89.408,142.968 89.408,142.709 89.479,142.638 89.835,142.638 89.906,142.568 89.906,142.309 89.835,142.238 89.479,142.238 89.408,142.168 89.408,141.909 89.479,141.838 89.88,141.838 89.95,141.768 89.95,141.509 89.88,141.438 89.479,141.438 89.408,141.368 89.408,141.109 89.479,141.038 89.907,141.038 89.977,140.968 89.977,140.709 89.907,140.638 89.479,140.638 89.408,140.568 89.408,140.309 89.479,140.238 89.952,140.238 90.022,140.168 90.022,139.909 89.952,139.838 89.479,139.838 89.408,139.768 89.408,139.554 89.479,139.483 89.887,139.483 89.958,139.412 89.958,139.154 89.887,139.083 89.479,139.083 89.408,139.012 89.408,138.754 89.479,138.683 89.887,138.683 89.958,138.612 89.958,138.354 89.887,138.283 89.479,138.283 89.1,137.904 89.1,125.276 v1(91.948,122.428)
$1N30089: R32.2 U2.24 | length 59
  Top Layer w0.1: v1(90.424,147.574) 90.984,147.574 R32.2@92.202,148.792 ; v1(91.694,121.793) 108.077,121.793 108.839,121.031 U2.24@110.114,121.031
  Bottom Layer w0.1: v1(90.424,147.574) 89.862,147.012 88.861,147.012 88.265,146.416 88.265,144.684 88.336,144.614 88.829,144.614 88.9,144.543 88.9,144.284 88.829,144.214 88.336,144.214 88.265,144.143 88.265,143.884 88.336,143.814 88.829,143.814 88.9,143.743 88.9,143.484 88.829,143.414 88.336,143.414 88.265,143.343 88.265,143.084 88.336,143.014 88.829,143.014 88.9,142.943 88.9,142.684 88.829,142.614 88.336,142.614 88.265,142.543 88.265,142.284 88.336,142.214 88.829,142.214 88.9,142.143 88.9,141.884 88.829,141.814 88.336,141.814 88.265,141.743 88.265,141.484 88.336,141.414 88.829,141.414 88.9,141.343 88.9,141.084 88.829,141.014 88.336,141.014 88.265,140.943 88.265,140.684 88.336,140.614 88.829,140.614 88.9,140.543 88.9,140.284 88.829,140.214 88.336,140.214 88.265,140.143 88.265,139.884 88.336,139.814 88.829,139.814 88.9,139.743 88.9,139.484 88.829,139.414 88.336,139.414 88.265,139.343 88.265,139.084 88.336,139.014 88.829,139.014 88.9,138.943 88.9,138.684 88.829,138.614 88.336,138.614 88.265,138.543 88.265,138.284 88.336,138.214 88.531,138.214 88.602,138.143 88.602,137.884 88.531,137.814 88.336,137.814 88.265,137.743 88.265,125.222 v1(91.694,121.793)
$1N30093: R28.2 U2.7 | length 59.1
  Top Layer w0.1: v1(86.393,147.828) 86.454,147.828 87.419,148.792 R28.2@87.63,148.792 ; U2.7@100.071,107.836 v1(100.071,108.839)
  Bottom Layer w0.1: v1(86.393,147.828) 85.725,147.16 85.725,146.916 85.796,146.845 85.908,146.845 85.979,146.774 85.979,146.516 85.908,146.445 85.796,146.445 85.725,146.374 85.725,146.116 85.796,146.045 85.908,146.045 85.979,145.974 85.979,145.716 85.908,145.645 85.796,145.645 85.725,145.574 85.725,145.316 85.796,145.245 85.908,145.245 85.979,145.174 85.979,144.916 85.908,144.845 85.796,144.845 85.725,144.774 85.725,144.516 85.796,144.445 85.908,144.445 85.979,144.374 85.979,144.116 85.908,144.045 85.796,144.045 85.725,143.974 85.725,143.716 85.796,143.645 85.908,143.645 85.979,143.574 85.979,143.316 85.908,143.245 85.796,143.245 85.725,143.174 85.725,142.916 85.796,142.845 85.908,142.845 85.979,142.774 85.979,142.516 85.908,142.445 85.796,142.445 85.725,142.374 85.725,142.116 85.796,142.045 85.908,142.045 85.979,141.974 85.979,141.716 85.908,141.645 85.796,141.645 85.725,141.574 85.725,141.324 85.796,141.253 86.035,141.253 86.106,141.182 86.106,140.924 86.035,140.853 85.796,140.853 85.725,140.782 85.725,140.524 85.796,140.453 86.035,140.453 86.106,140.382 86.106,140.124 86.035,140.053 85.796,140.053 85.725,139.982 85.725,110.109 86.995,108.839 v1(100.071,108.839)
$1N33205: P1.8 R35.1 | length 1.9
  Top Layer w0.1: R35.1@117.094,173.788 117.135,173.828 P1.8@117.135,175.655
$1N60668: C64.1 U11.6 | length 1.6
  Top Layer w0.5: U11.6@111.766,95.537 111.766,95.844 112.499,96.578 112.776,96.578
$1N60669: C64.2 L3.1 U11.5 | length 3.6
  Top Layer w0.1: L3.1@113.442,94.587 L3.1@113.541,94.488
  Top Layer w0.5: U11.5@111.766,94.587 L3.1@113.442,94.587 ; 112.821,95.954 113.541,95.234 L3.1@113.541,94.488
$1N60670: C65.1 R40.2 R41.1 U11.1 | length 8
  Top Layer w0.1: U11.1@109.066,95.537 109.822,95.537 110.626,94.733 R40.2@110.626,88.646
$1N63749: R43.1 USB2.A5 | length 6.1
  Top Layer w0.1: R43.1@99.305,90.17 99.432,90.043 v1(100.203,90.043) ; v1(103.779,91.186) USB2.A5@103.779,92.278
  Bottom Layer w0.1: v1(100.203,90.043) 102.636,90.043 v1(103.779,91.186)
$1N63772: R42.1 USB2.B5 | length 10.5
  Top Layer w0.1: R42.1@99.305,88.646 100.076,88.646 v1(100.203,88.773) ; USB2.B5@106.779,92.278 106.807,92.251 v1(106.807,91.313)
  Bottom Layer w0.1: v1(100.203,88.773) 100.965,89.535 106.553,89.535 106.581,89.563 106.581,91.087 v1(106.807,91.313)
$1N63825: R44.2 USB2.A4B9 USB2.B4A9 | length 12.3
  Top Layer w0.1: USB2.A4B9@102.629,92.278 102.87,92.037 v1(102.87,91.059) 103.309,90.62 107.13,90.62 107.392,90.882 107.392,92.241 USB2.B4A9@107.429,92.278 ; v1(103.759,94.361) 104.639,94.361 R44.2@104.775,94.497
  Bottom Layer w0.1: v1(102.87,91.059) 102.87,93.472 v1(103.759,94.361)
$1N64401: C69.2 L4.1 U12.5 | length 3.6
  Top Layer w0.4: C69.2@126.373,93.599 127.003,92.969 L4.1@127.003,91.821
  Top Layer w0.5: U12.5@125.429,91.821 L4.1@127.003,91.821
$1N64402: C69.1 U12.6 | length 1
  Top Layer w0.4: U12.6@125.429,92.771 125.429,93.179 C69.1@125.849,93.599
$1N64403: C70.1 R46.2 R47.1 U12.1 | length 10.6
  Top Layer w0.1: R46.2@121.149,87.63 122.617,87.63 C70.1@122.744,87.757 ; U12.1@122.729,92.771 122.79,92.71 122.976,92.71 123.481,92.205 123.481,90.487 122.744,89.75 C70.1@122.744,87.757 ; R47.1@125.678,86.995 123.506,86.995 C70.1@122.744,87.757
$2N5507: R23.2 U1.P10 | length 20.1
  Top Layer w0.1: R23.2@91.238,151.13 93.853,151.13 93.959,151.024 93.959,150.836 94.575,150.22 96.795,150.22 v1(97.155,149.86)
  Top Layer w0.254: U1.P10@109.277,148.889 109.601,149.213 v1@109.601,149.225
  Bottom Layer w0.254: v1(97.155,149.86) 107.507,149.86 107.986,149.381 107.986,149.159 108.127,149.018 109.073,149.018 109.173,148.918 109.294,148.918 v1(109.622,149.246)
$2N5509: R24.2 U1.N10 | length 24
  Top Layer w0.1: v1(94.869,149.818) 96.628,149.818 96.988,149.458 97.322,149.458 97.682,149.818 97.875,149.818 99.119,151.062 99.119,151.067 99.759,151.707 102.199,151.707 102.495,151.411 102.495,151.131 102.755,150.871 103.091,150.871 103.295,150.667 103.295,150.331 103.519,150.107 105.435,150.107 105.442,150.114 105.912,150.114 105.919,150.107 106.235,150.107 106.459,150.331 106.459,150.689 106.641,150.871 107.835,150.871 108.095,150.611 108.095,149.531 108.319,149.307 108.895,149.307 U1.N10@109.277,149.689
  Top Layer w0.254: R24.2@93.397,153.67 94.286,152.781 v1(95.123,152.781)
  Bottom Layer w0.1: v1(94.869,149.818) 94.615,150.072 94.615,150.697 95.323,151.405 95.323,151.829 95.25,151.902 95.25,152.146 95.123,152.273 v1(95.123,152.781)
$2N5511: R25.2 U1.R10 | length 7.9
  Top Layer w0.1: R25.2@104.648,142.546 v1(104.648,143.383) ; v1(108.077,147.701) 108.889,147.701 U1.R10@109.277,148.089
  Bottom Layer w0.1: v1(104.648,143.383) 107.929,146.664 107.929,146.852 108.077,147 v1(108.077,147.701)
+1V1: C25.2 C27.2 C28.2 C41.1 C42.1 C43.1 C44.1 C49.1 C53.1 C54.1 C61.1 L2.2 R15.2 U1.G6 U1.G7 U1.L8 U1.L9 U1.L10 | length 71.4
  Top Layer w0.1: v1@105.664,154.94 105.664,154.902 U1.G6@106.077,154.489 U1.G7@106.877,154.489 ; U1.L8@107.677,151.289 U1.L9@108.477,151.289 108.543,151.289 v1(108.936,150.897) 109.277,151.238 U1.L10@109.277,151.289
  Top Layer w1: R15.2@115.198,123.444 115.124,123.518 C25.2@115.124,125.222 115.124,127.316 v2(115.824,128.016) ; C27.2@115.824,133.031 C28.2@117.602,133.031
  Top Layer w1.5: v2(115.824,128.016) L2.2@117.904,128.016 117.602,128.318 C28.2@117.602,133.031
  Inner2 w0.7: 105.232,154.932 v1(105.672,154.932)
  Inner2 w0.8: v1(104.086,153.249) v1@104.077,153.258 ; 105.232,154.932 105.21,154.909 105.111,154.909 104.077,153.875 v1@104.077,153.258 ; v1@105.672,154.909 105.777,154.805 106.053,154.805 106.069,154.789 108.815,154.789 v1(108.92,154.894) ; v1@106.436,152.302 106.125,151.99 106.125,150.859 105.705,150.439 104.877,150.439 104.077,151.239 v1@104.077,153.258
  Inner2 w1.5: 106.125,150.859 106.172,150.812 106.172,148.785 105.895,148.508 105.895,145.311 v2(114.173,137.033) v2(114.173,131.972) 114.173,129.667 v2(115.824,128.016)
  Bottom Layer w0.2: 105.475,153.518 C61.1@105.475,154.051 106.24,154.051 C41.1@106.299,154.11 106.607,154.11 106.986,154.489 107.461,154.489 107.661,154.289 108.082,154.289 C42.1@108.342,154.548 108.458,154.432 108.78,154.432 109.542,155.194 ; v1(106.514,152.479) 106.642,152.479 106.736,152.385 106.736,152.381 106.842,152.275 106.842,151.859 C54.1@106.748,151.765 106.748,151.316 107.061,151.003 107.819,151.003 108.073,150.749 108.788,150.749 108.801,150.762 v1@108.936,150.762 ; C53.1@108.653,151.13 108.78,151.003 108.839,151.003 108.907,150.935 C49.1@108.907,152.019 ; C43.1@109.542,155.448 109.542,155.194 ; C44.1@110.558,154.178 110.525,154.211 110.525,154.392 110.377,154.54 110.196,154.54 109.542,155.194
  Bottom Layer w0.4: 105.475,153.409 106.405,152.479 v1(106.514,152.479) ; 105.475,153.518 105.475,152.716 v1(105.666,152.525)
  other v1: 105.791,146.812 105.664,147.701 106.527,147.689 106.526,148.489 105.661,148.508 105.726,149.289 106.508,149.306 105.727,151.69 104.926,154.888
+1V8: C29.1 C32.2 C35.1 C62.1 C63.1 P1.11 pad.55@123.394,105.627 R38.2 R39.2 U1.F10 U1.F11 U8.2 | length 126.2
  Top Layer w0.1: v1(109.709,156.504) 109.709,156.262 109.695,156.247 109.695,155.931 109.709,155.917 109.709,155.721 U1.F10@109.277,155.289 U1.F11@110.077,155.289 ; R38.2@113.665,172.668 113.665,172.205 113.661,172.201 113.661,171.2 113.792,171.069 114.574,171.069 116.173,172.668 116.509,172.668 ; R39.2@115.062,172.795 116.382,172.795 116.509,172.668 ; P1.11@118.634,175.655 118.733,175.557 118.733,174.458 118.745,174.446 C35.1@118.745,173.931 ; 118.856,173.931 119.057,173.73 119.057,173.352 118.639,172.934 118.639,172.756 118.321,172.437 116.74,172.437 116.509,172.668
  Top Layer w0.254: C29.1@124.011,106.68 121.943,106.68 122.996,105.627 pad.55@123.394,105.627 C32.2@125.349,105.627
  Top Layer w0.3: v2(118.11,178.054) 118.634,177.53 P1.11@118.634,175.655
  Top Layer w1: v2(119.761,113.03) 119.761,107.315 120.367,106.709 U8.2@121.914,106.709
  Inner2 w0.5: v1(107.325,155.689) 107.362,155.689 108.178,156.504 v1(109.709,156.504) 109.888,156.683 109.888,156.713 110.75,157.575 115.411,157.575
  Inner2 w1: 115.411,157.575 116.967,159.131 116.967,161.417 111.887,166.497 111.887,177.71 113.21,179.033 117.131,179.033 v2(118.11,178.054)
  Inner2 w1.5: 115.411,157.575 130.429,142.558 v2(130.429,134.939) 130.429,123.698 v2(128.27,121.539) v2(119.761,113.03)
  Bottom Layer w0.1: C63.1@106.807,155.761 107.253,155.761 v1(107.325,155.689) 106.934,155.298 C62.1@106.934,155.262
+2V5: C65.2 C67.2 C68.2 L3.2 R41.2 U1.G11 U1.L7 | length 91.3
  Top Layer w0.1: U1.L7@106.877,151.289 107.137,151.289 107.555,151.707 109.435,151.707 109.659,151.931 109.659,152.247 109.629,152.277 v1(109.629,152.489) ; v1(109.629,154.089) 110.029,154.489 U1.G11@110.077,154.489
  Top Layer w0.5: R41.2@111.431,90.043 111.825,90.437 C65.2@111.825,91.567
  Top Layer w1: C65.2@111.825,91.567 114.17,91.567 L3.2@117.091,94.488 ; v2(117.091,97.282) L3.2@117.091,94.488 ; C67.2@120.523,92.394 C68.2@118.745,92.394 118.745,92.834 L3.2@117.091,94.488
  Inner2 w0.5: v1(109.629,152.489) v1(109.629,154.089)
  Inner2 w0.7: v1(109.629,154.089) 109.718,154.178 112.649,154.178
  Inner2 w1: 112.649,154.178 117.091,149.736
  Inner2 w1.5: v2(117.091,97.282) 117.091,115.186 127,125.095 127,134.62 117.091,144.529 117.091,149.736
